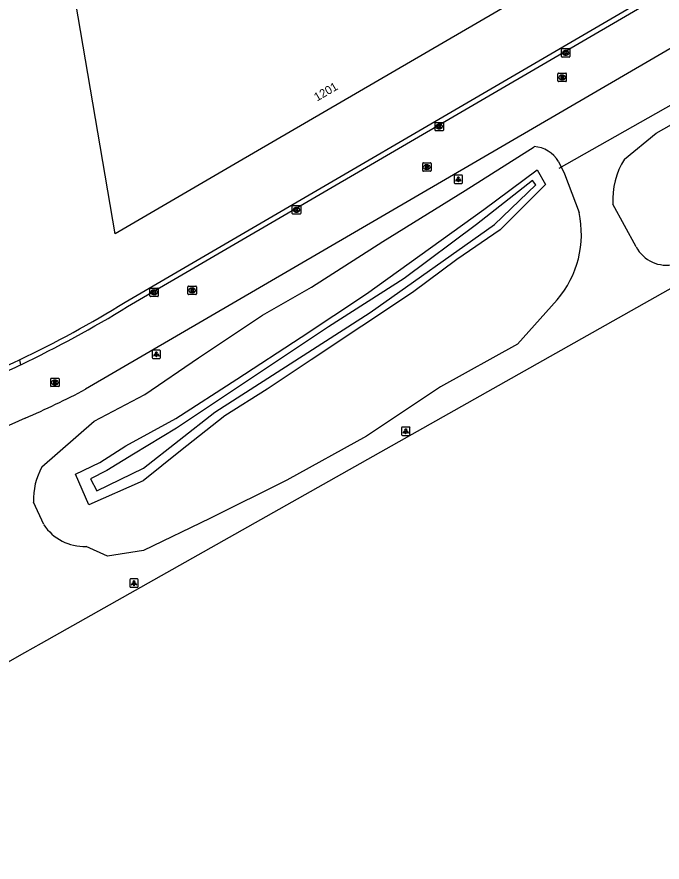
# Model space of a CAD drawing. Extents: x 154324 to 155743, y 382939 to 384183.
# Drawn here: x 154702 to 154778.5, y 382988.6 to 383088.8 of the extents above; entities that cross this region are included whole.
import ezdxf

# ---------------------------------------------------------------- set-up
doc = ezdxf.new("R2010")
doc.units = 0
for name, color, linetype in [('IMGEO_Berm_groen', 7, 'Continuous'), ('IMGEO_Duiker', 7, 'Continuous'), ('IMGEO_Fietspad_gesloten', 7, 'Continuous'), ('IMGEO_Groenvoorziening', 7, 'Continuous'), ('IMGEO_Kolk', 7, 'Continuous'), ('IMGEO_Lichtpunt', 7, 'Continuous'), ('IMGEO_Pand', 7, 'Continuous'), ('IMGEO_Pand_nummerreeks', 7, 'Continuous'), ('IMGEO_Rijbaan_lokaal_gesloten', 7, 'Continuous'), ('IMGEO_Rioolput', 7, 'Continuous'), ('IMGEO_Waterloop', 7, 'Continuous')]:
    doc.layers.add(name, color=color, linetype=linetype)

msp = doc.modelspace()

# ---------------------------------------------------------------- linework, layer by layer
at = {"layer": 'IMGEO_Berm_groen'}
for points in [[(154774.07, 383071.9), (154777.85, 383074.99), (154783.84, 383078.37), (154788.17, 383079.96), (154794.61, 383083.05), (154800.57, 383084.89)], [(154704.99, 383035.41), (154711.18, 383040.82), (154717.2, 383044.01), (154723.57, 383048.33), (154731.15, 383053.4), (154736.97, 383056.74), (154745.44, 383062.14), (154755.2, 383068.2), (154763.36, 383073.38)], [(154766.25, 383071.61), (154766.97, 383070.16), (154768.7, 383065.57)], [(154775.46, 383061.52), (154772.71, 383066.56)], [(154766.11, 383055.24), (154761.41, 383049.96), (154752.25, 383044.92), (154743.48, 383039.05), (154734.02, 383033.85), (154724.9, 383029.28), (154717.04, 383025.52), (154712.79, 383024.83), (154710.23, 383025.99)], [(154705.21, 383028.57), (154703.99, 383031.24)]]:
    msp.add_lwpolyline(points, dxfattribs=at)
for centre, radius, start, end in [((154763.18, 383069.85), 3.54, 29.8809, 87.1189), ((154781.76, 383067.09), 9.07, 147.9556, 183.3621), ((154756.95, 383063.02), 12.02, 319.6553, 12.2487), ((154779.02, 383063.34), 4, 207.0616, 284.7098), ((154711.96, 383031.54), 7.97, 150.9388, 182.1612), ((154710.06, 383031.82), 5.84, 213.8608, 271.6652)]:
    msp.add_arc(centre, radius, start, end, dxfattribs=at)
at = {"layer": 'IMGEO_Duiker'}
msp.add_lwpolyline([(154808.78, 383094.87), (154766.28, 383070.8)], dxfattribs=at)
at = {"layer": 'IMGEO_Fietspad_gesloten'}
msp.add_lwpolyline([(154658.95, 382988.56), (154668.99, 382994.18), (154672.72, 382996.39), (154679.21, 383000), (154680.53, 383000.75), (154684.21, 383002.82), (154689.55, 383005.83), (154693, 383007.77), (154702.97, 383013.4), (154704.95, 383014.51), (154806.83, 383071.94)], dxfattribs=at)
at = {"layer": 'IMGEO_Groenvoorziening'}
msp.add_lwpolyline([(154764.71, 383068.91), (154759.33, 383063.52), (154754.19, 383059.99), (154748.93, 383056.1), (154736.91, 383048.11), (154731.7, 383044.62), (154726.67, 383041.48), (154721.41, 383037.31), (154716.99, 383033.77), (154710.57, 383030.92), (154708.97, 383034.57), (154711.87, 383035.94), (154714.93, 383037.91), (154720.86, 383041.15), (154728.1, 383045.83), (154735.72, 383050.79), (154743.49, 383055.92), (154757.39, 383065.94), (154763.74, 383070.64), (154764.71, 383068.91)], dxfattribs=at)
at = {"layer": 'IMGEO_Kolk'}
for p, q in [((154766.61, 383084.08), (154766.61, 383084.94)), ((154766.68, 383085.01), (154767.54, 383085.01)), ((154767.12, 383084.23), (154767.09, 383084.23)), ((154767.1, 383084.79), (154767.12, 383084.79)), ((154767.61, 383084.94), (154767.61, 383084.08)), ((154767.54, 383084.01), (154766.68, 383084.01)), ((154751.61, 383075.35), (154751.61, 383076.2)), ((154751.68, 383076.27), (154752.54, 383076.27)), ((154752.61, 383076.2), (154752.61, 383075.35)), ((154752.54, 383075.27), (154751.68, 383075.27)), ((154752.12, 383075.49), (154752.09, 383075.49)), ((154752.1, 383076.05), (154752.12, 383076.05)), ((154734.68, 383065.47), (154734.68, 383066.32)), ((154734.75, 383066.4), (154735.61, 383066.4)), ((154735.17, 383066.18), (154735.19, 383066.18)), ((154735.68, 383066.32), (154735.68, 383065.47)), ((154735.61, 383065.4), (154734.75, 383065.4)), ((154735.19, 383065.62), (154735.16, 383065.62)), ((154717.79, 383055.69), (154717.79, 383056.55)), ((154717.87, 383056.62), (154718.72, 383056.62)), ((154718.28, 383056.4), (154718.31, 383056.4)), ((154718.8, 383056.55), (154718.8, 383055.69)), ((154718.72, 383055.62), (154717.87, 383055.62)), ((154718.3, 383055.84), (154718.28, 383055.84))]:
    msp.add_line(p, q, dxfattribs=at)
for points in [[(154766.61, 383084.08), (154766.61, 383084.94)], [(154766.68, 383085.01), (154767.54, 383085.01)], [(154766.93, 383084.71), (154767.05, 383084.71), (154767.05, 383084.56), (154767.18, 383084.71), (154767.35, 383084.71), (154767.2, 383084.56), (154767.35, 383084.31), (154767.2, 383084.31), (154767.12, 383084.47), (154767.05, 383084.41), (154767.05, 383084.31), (154766.93, 383084.31), (154766.93, 383084.71)], [(154767.61, 383084.94), (154767.61, 383084.08)], [(154767.54, 383084.01), (154766.68, 383084.01)], [(154751.61, 383075.35), (154751.61, 383076.2)], [(154751.68, 383076.27), (154752.54, 383076.27)], [(154752.61, 383076.2), (154752.61, 383075.35)], [(154752.54, 383075.27), (154751.68, 383075.27)], [(154751.93, 383075.97), (154752.05, 383075.97), (154752.05, 383075.82), (154752.18, 383075.97), (154752.35, 383075.97), (154752.2, 383075.82), (154752.35, 383075.57), (154752.2, 383075.57), (154752.12, 383075.74), (154752.05, 383075.67), (154752.05, 383075.57), (154751.93, 383075.57), (154751.93, 383075.97)], [(154734.68, 383065.47), (154734.68, 383066.32)], [(154734.75, 383066.4), (154735.61, 383066.4)], [(154735, 383066.1), (154735.12, 383066.1), (154735.12, 383065.95), (154735.25, 383066.1), (154735.42, 383066.1), (154735.27, 383065.95), (154735.42, 383065.7), (154735.27, 383065.7), (154735.19, 383065.86), (154735.12, 383065.8), (154735.12, 383065.7), (154735, 383065.7), (154735, 383066.1)], [(154735.68, 383066.32), (154735.68, 383065.47)], [(154735.61, 383065.4), (154734.75, 383065.4)], [(154717.79, 383055.69), (154717.79, 383056.55)], [(154717.87, 383056.62), (154718.72, 383056.62)], [(154718.11, 383056.32), (154718.24, 383056.32), (154718.24, 383056.17), (154718.37, 383056.32), (154718.53, 383056.32), (154718.39, 383056.17), (154718.54, 383055.92), (154718.39, 383055.92), (154718.3, 383056.08), (154718.24, 383056.02), (154718.24, 383055.92), (154718.11, 383055.92), (154718.11, 383056.32)], [(154718.8, 383056.55), (154718.8, 383055.69)], [(154718.72, 383055.62), (154717.87, 383055.62)]]:
    msp.add_lwpolyline(points, dxfattribs=at)
for centre, start, end in [((154766.68, 383084.93), 91.552, 178.448), ((154766.68, 383084.93), 91.552, 178.448), ((154766.68, 383084.09), 181.552, 268.448), ((154766.68, 383084.09), 181.552, 268.448), ((154767.53, 383084.93), 1.552, 88.448), ((154767.53, 383084.93), 1.552, 88.448), ((154767.53, 383084.09), 271.552, 358.448), ((154767.53, 383084.09), 271.552, 358.448), ((154751.69, 383076.2), 91.552, 178.448), ((154751.69, 383076.2), 91.552, 178.448), ((154752.53, 383076.2), 1.552, 88.448), ((154752.53, 383076.2), 1.552, 88.448), ((154751.69, 383075.35), 181.552, 268.448), ((154751.69, 383075.35), 181.552, 268.448), ((154752.53, 383075.35), 271.552, 358.448), ((154752.53, 383075.35), 271.552, 358.448), ((154734.75, 383066.32), 91.552, 178.448), ((154734.75, 383066.32), 91.552, 178.448), ((154735.6, 383066.32), 1.552, 88.448), ((154735.6, 383066.32), 1.552, 88.448), ((154734.75, 383065.47), 181.552, 268.448), ((154734.75, 383065.47), 181.552, 268.448), ((154735.6, 383065.47), 271.552, 358.448), ((154735.6, 383065.47), 271.552, 358.448), ((154717.87, 383056.54), 91.552, 178.448), ((154717.87, 383056.54), 91.552, 178.448), ((154718.72, 383056.54), 1.552, 88.448), ((154718.72, 383056.54), 1.552, 88.448), ((154717.87, 383055.69), 181.552, 268.448), ((154717.87, 383055.69), 181.552, 268.448), ((154718.72, 383055.69), 271.552, 358.448), ((154718.72, 383055.69), 271.552, 358.448)]:
    msp.add_arc(centre, 0.0765, start, end, dxfattribs=at)
for centre, major_axis, ratio, start_param, end_param in [((154767.1, 383084.51), (-0.387, 0.002), 0.722429, 4.712389, 7.853982), ((154767.12, 383084.51), (-0.39, 0.002), 0.717154, 1.570796, 4.712389), ((154752.1, 383075.77), (-0.387, 0.002), 0.722429, 4.712389, 7.853982), ((154752.12, 383075.77), (-0.39, 0.002), 0.717154, 1.570796, 4.712389), ((154735.17, 383065.9), (-0.387, 0.002), 0.722429, 4.712389, 7.853982), ((154735.19, 383065.9), (-0.39, 0.002), 0.717154, 1.570796, 4.712389), ((154718.28, 383056.12), (-0.387, 0.002), 0.722429, 4.712389, 7.853982), ((154718.31, 383056.12), (-0.39, 0.002), 0.717154, 1.570796, 4.712389)]:
    msp.add_ellipse(centre, major_axis=major_axis, ratio=ratio, start_param=start_param, end_param=end_param, dxfattribs=at)
at = {"layer": 'IMGEO_Lichtpunt'}
for p, q in [((154753.88, 383069.92), (154753.88, 383069.11)), ((154753.88, 383069.92), (154753.88, 383069.11)), ((154754.78, 383070.01), (154753.97, 383070.01)), ((154754.78, 383070.01), (154753.97, 383070.01)), ((154754.88, 383069.11), (154754.88, 383069.92)), ((154754.88, 383069.11), (154754.88, 383069.92)), ((154753.97, 383069.02), (154754.78, 383069.02)), ((154753.97, 383069.02), (154754.78, 383069.02)), ((154718.07, 383049.17), (154718.07, 383048.37)), ((154718.07, 383049.17), (154718.07, 383048.37)), ((154718.97, 383049.27), (154718.16, 383049.27)), ((154718.97, 383049.27), (154718.16, 383049.27)), ((154719.06, 383048.37), (154719.06, 383049.17)), ((154719.06, 383048.37), (154719.06, 383049.17)), ((154718.16, 383048.27), (154718.97, 383048.27)), ((154718.16, 383048.27), (154718.97, 383048.27)), ((154747.64, 383040.05), (154747.64, 383039.24)), ((154747.64, 383040.05), (154747.64, 383039.24)), ((154748.55, 383040.14), (154747.74, 383040.14)), ((154748.55, 383040.14), (154747.74, 383040.14)), ((154748.64, 383039.24), (154748.64, 383040.05)), ((154748.64, 383039.24), (154748.64, 383040.05)), ((154747.74, 383039.15), (154748.55, 383039.15)), ((154747.74, 383039.15), (154748.55, 383039.15)), ((154715.42, 383022.04), (154715.42, 383021.23)), ((154715.42, 383022.04), (154715.42, 383021.23)), ((154716.32, 383022.13), (154715.51, 383022.13)), ((154716.32, 383022.13), (154715.51, 383022.13)), ((154716.41, 383021.23), (154716.41, 383022.04)), ((154716.41, 383021.23), (154716.41, 383022.04)), ((154715.51, 383021.14), (154716.32, 383021.14)), ((154715.51, 383021.14), (154716.32, 383021.14))]:
    msp.add_line(p, q, dxfattribs=at)
for points in [[(154754.25, 383069.58), (154754.29, 383069.55), (154754.1, 383069.29), (154754.07, 383069.32), (154754.25, 383069.58)], [(154754.35, 383069.53), (154754.4, 383069.53), (154754.4, 383069.21), (154754.35, 383069.21), (154754.35, 383069.53)], [(154754.46, 383069.55), (154754.5, 383069.58), (154754.69, 383069.32), (154754.65, 383069.29), (154754.46, 383069.55)], [(154718.44, 383048.84), (154718.48, 383048.81), (154718.29, 383048.55), (154718.25, 383048.57), (154718.44, 383048.84)], [(154718.54, 383048.79), (154718.59, 383048.79), (154718.59, 383048.47), (154718.54, 383048.47), (154718.54, 383048.79)], [(154718.65, 383048.81), (154718.69, 383048.84), (154718.88, 383048.57), (154718.84, 383048.55), (154718.65, 383048.81)], [(154748.02, 383039.71), (154748.06, 383039.68), (154747.87, 383039.42), (154747.83, 383039.45), (154748.02, 383039.71)], [(154748.12, 383039.66), (154748.17, 383039.66), (154748.17, 383039.34), (154748.12, 383039.34), (154748.12, 383039.66)], [(154748.23, 383039.68), (154748.27, 383039.71), (154748.46, 383039.45), (154748.42, 383039.42), (154748.23, 383039.68)], [(154715.79, 383021.7), (154715.83, 383021.67), (154715.64, 383021.41), (154715.6, 383021.44), (154715.79, 383021.7)], [(154715.89, 383021.65), (154715.94, 383021.65), (154715.94, 383021.33), (154715.89, 383021.33), (154715.89, 383021.65)], [(154716, 383021.67), (154716.04, 383021.7), (154716.23, 383021.44), (154716.19, 383021.41), (154716, 383021.67)]]:
    msp.add_lwpolyline(points, dxfattribs=at)
for centre in [(154754.38, 383069.72), (154718.57, 383048.97), (154748.14, 383039.85), (154715.92, 383021.84)]:
    msp.add_circle(centre, 0.0994, dxfattribs=at)
for centre, start, end in [((154753.97, 383069.92), 90, 180), ((154753.97, 383069.92), 90, 180), ((154753.97, 383069.11), 180, 270), ((154753.97, 383069.11), 180, 270), ((154754.78, 383069.92), 0, 90), ((154754.78, 383069.92), 0, 90), ((154754.78, 383069.11), 270, 0), ((154754.78, 383069.11), 270, 360), ((154718.16, 383049.17), 90, 180), ((154718.16, 383049.17), 90, 180), ((154718.97, 383049.17), 0, 90), ((154718.97, 383049.17), 0, 90), ((154718.16, 383048.37), 180, 270), ((154718.16, 383048.37), 180, 270), ((154718.97, 383048.37), 270, 0), ((154718.97, 383048.37), 270, 360), ((154747.74, 383040.05), 90, 180), ((154747.74, 383040.05), 90, 180), ((154748.55, 383040.05), 0, 90), ((154748.55, 383040.05), 0, 90), ((154747.74, 383039.24), 180, 270), ((154747.74, 383039.24), 180, 270), ((154748.55, 383039.24), 270, 0), ((154748.55, 383039.24), 270, 360), ((154715.51, 383022.04), 90, 180), ((154715.51, 383022.04), 90, 180), ((154716.32, 383022.04), 0, 90), ((154716.32, 383022.04), 0, 90), ((154715.51, 383021.23), 180, 270), ((154715.51, 383021.23), 180, 270), ((154716.32, 383021.23), 270, 0), ((154716.32, 383021.23), 270, 360)]:
    msp.add_arc(centre, 0.0946, start, end, dxfattribs=at)
at = {"layer": 'IMGEO_Pand'}
msp.add_lwpolyline([(154761.55, 383202.29), (154766.47, 383173.5), (154749.73, 383170.63), (154750.57, 383165.74), (154750.63, 383165.35), (154755.3, 383137.94), (154772.04, 383140.8), (154777.71, 383107.67), (154758.43, 383104.38), (154760.79, 383090.49), (154728.38, 383071.61), (154713.67, 383063.04), (154708.1, 383095.79), (154696.76, 383093.86), (154680.67, 383188.5)], dxfattribs=at)
at = {"layer": 'IMGEO_Rijbaan_lokaal_gesloten'}
for points in [[(154991.53, 383204.59), (154991.29, 383204.46), (154988.64, 383202.93), (154972.99, 383194.07), (154922.65, 383165.82), (154870.56, 383136.48), (154807.99, 383101.45), (154807.41, 383100.98), (154799.35, 383096.59), (154796.65, 383095.01), (154788.62, 383090.34), (154781.16, 383085.99), (154710.18, 383044.63)], [(154714.85, 383054.94), (154776.27, 383090.74)], [(154715.15, 383054.43), (154776.57, 383090.26)], [(154641.36, 383020.72), (154644.06, 383021.92), (154701.68, 383047.8), (154702.34, 383048.11)], [(154702.34, 383048.11), (154702.47, 383047.53)], [(154641.57, 383020.14), (154644.31, 383021.37), (154701.89, 383047.26), (154702.47, 383047.53)], [(154703.01, 383041.2), (154652.03, 383018.31), (154642.78, 383014.08)]]:
    msp.add_lwpolyline(points, dxfattribs=at)
for centre, radius, start, end in [((154645.72, 383166.64), 131.36, 295.5332, 301.7538), ((154643.8, 383170.52), 136.27, 295.5044, 301.5752), ((154660.3, 383139.67), 107.34, 293.4434, 297.6884)]:
    msp.add_arc(centre, radius, start, end, dxfattribs=at)
at = {"layer": 'IMGEO_Rioolput'}
for p, q in [((154766.26, 383082.1), (154767.11, 383082.1)), ((154766.18, 383081.18), (154766.18, 383082.03)), ((154767.11, 383081.1), (154766.26, 383081.1)), ((154766.67, 383081.88), (154766.69, 383081.88)), ((154766.69, 383081.32), (154766.67, 383081.32)), ((154767.18, 383082.03), (154767.18, 383081.18)), ((154750.15, 383070.55), (154750.15, 383071.4)), ((154750.23, 383071.47), (154751.08, 383071.47)), ((154750.64, 383071.25), (154750.67, 383071.25)), ((154751.15, 383071.4), (154751.15, 383070.55)), ((154751.08, 383070.47), (154750.23, 383070.47)), ((154750.66, 383070.69), (154750.64, 383070.69)), ((154722.31, 383055.93), (154722.31, 383056.78)), ((154722.39, 383056.85), (154723.24, 383056.85)), ((154722.8, 383056.63), (154722.83, 383056.63)), ((154722.82, 383056.07), (154722.8, 383056.07)), ((154723.31, 383056.78), (154723.31, 383055.93)), ((154723.24, 383055.85), (154722.39, 383055.85)), ((154706.04, 383045), (154706.04, 383045.85)), ((154706.11, 383045.93), (154706.96, 383045.93)), ((154706.52, 383045.71), (154706.55, 383045.71)), ((154706.55, 383045.15), (154706.52, 383045.15)), ((154707.04, 383045.85), (154707.04, 383045)), ((154706.96, 383044.93), (154706.11, 383044.93))]:
    msp.add_line(p, q, dxfattribs=at)
for points in [[(154766.26, 383082.1), (154767.11, 383082.1)], [(154766.18, 383081.18), (154766.18, 383082.03)], [(154767.11, 383081.1), (154766.26, 383081.1)], [(154766.77, 383081.8), (154766.52, 383081.8), (154766.52, 383081.4)], [(154766.52, 383081.4), (154766.64, 383081.4), (154766.64, 383081.57), (154766.65, 383081.57)], [(154766.7, 383081.72), (154766.64, 383081.72), (154766.64, 383081.64)], [(154766.64, 383081.64), (154766.69, 383081.64)], [(154766.7, 383081.54), (154766.77, 383081.4), (154766.91, 383081.4), (154766.85, 383081.53)], [(154767.18, 383082.03), (154767.18, 383081.18)], [(154750.15, 383070.55), (154750.15, 383071.4)], [(154750.23, 383071.47), (154751.08, 383071.47)], [(154750.74, 383071.17), (154750.49, 383071.17), (154750.49, 383070.77)], [(154750.67, 383071.09), (154750.61, 383071.09), (154750.61, 383071.01)], [(154751.15, 383071.4), (154751.15, 383070.55)], [(154751.08, 383070.47), (154750.23, 383070.47)], [(154750.49, 383070.77), (154750.61, 383070.77), (154750.61, 383070.93), (154750.62, 383070.93)], [(154750.61, 383071.01), (154750.66, 383071.01)], [(154750.67, 383070.9), (154750.74, 383070.77), (154750.88, 383070.77), (154750.82, 383070.9)], [(154722.31, 383055.93), (154722.31, 383056.78)], [(154722.39, 383056.85), (154723.24, 383056.85)], [(154722.9, 383056.55), (154722.65, 383056.55), (154722.65, 383056.15)], [(154722.65, 383056.15), (154722.77, 383056.15), (154722.77, 383056.32), (154722.78, 383056.32)], [(154722.83, 383056.47), (154722.77, 383056.47), (154722.77, 383056.39)], [(154722.77, 383056.39), (154722.82, 383056.39)], [(154722.83, 383056.29), (154722.9, 383056.15), (154723.04, 383056.15), (154722.98, 383056.28)], [(154723.31, 383056.78), (154723.31, 383055.93)], [(154723.24, 383055.85), (154722.39, 383055.85)], [(154706.04, 383045), (154706.04, 383045.85)], [(154706.11, 383045.93), (154706.96, 383045.93)], [(154706.62, 383045.62), (154706.37, 383045.63), (154706.37, 383045.23)], [(154706.37, 383045.23), (154706.5, 383045.23), (154706.5, 383045.39), (154706.51, 383045.39)], [(154706.55, 383045.55), (154706.5, 383045.55), (154706.5, 383045.46)], [(154706.5, 383045.46), (154706.55, 383045.46)], [(154706.55, 383045.36), (154706.63, 383045.23), (154706.76, 383045.23), (154706.7, 383045.35)], [(154707.04, 383045.85), (154707.04, 383045)], [(154706.96, 383044.93), (154706.11, 383044.93)]]:
    msp.add_lwpolyline(points, dxfattribs=at)
for centre, radius, start, end in [((154766.26, 383082.03), 0.0765, 91.552, 178.448), ((154766.26, 383082.03), 0.0765, 91.552, 178.448), ((154767.11, 383082.03), 0.0765, 1.552, 88.448), ((154767.11, 383082.03), 0.0765, 1.552, 88.448), ((154766.26, 383081.18), 0.0765, 181.552, 268.448), ((154766.26, 383081.18), 0.0765, 181.552, 268.448), ((154766.65, 383081.51), 0.0533, 26.0293, 88.6989), ((154766.68, 383081.83), 0.19, 274.7715, 282.9687), ((154766.7, 383081.63), 0.0964, 77.0061, 93.1865), ((154766.72, 383081.68), 0.0378, 276.6634, 79.6772), ((154766.77, 383081.69), 0.109, 350.3612, 89.416), ((154766.77, 383081.69), 0.112, 277.5842, 350.9817), ((154766.75, 383081.48), 0.108, 29.5134, 73.7905), ((154767.11, 383081.18), 0.0765, 271.552, 358.448), ((154767.11, 383081.18), 0.0765, 271.552, 358.448), ((154750.23, 383071.4), 0.0765, 91.552, 178.448), ((154750.23, 383071.4), 0.0765, 91.552, 178.448), ((154750.67, 383070.99), 0.0964, 77.0061, 93.1865), ((154750.69, 383071.05), 0.0378, 276.6634, 79.6772), ((154750.74, 383071.06), 0.109, 350.3612, 89.416), ((154751.08, 383071.4), 0.0765, 1.552, 88.448), ((154751.08, 383071.4), 0.0765, 1.552, 88.448), ((154750.23, 383070.55), 0.0765, 181.552, 268.448), ((154750.23, 383070.55), 0.0765, 181.552, 268.448), ((154750.62, 383070.88), 0.0533, 26.0293, 88.6989), ((154750.65, 383071.2), 0.19, 274.7715, 282.9687), ((154750.74, 383071.06), 0.112, 277.5842, 350.9817), ((154750.72, 383070.84), 0.108, 29.5134, 73.7905), ((154751.08, 383070.55), 0.0765, 271.552, 358.448), ((154751.08, 383070.55), 0.0765, 271.552, 358.448), ((154722.39, 383056.78), 0.0765, 91.552, 178.448), ((154722.39, 383056.78), 0.0765, 91.552, 178.448), ((154722.78, 383056.26), 0.0533, 26.0293, 88.6989), ((154722.81, 383056.58), 0.19, 274.7715, 282.9687), ((154722.83, 383056.38), 0.0964, 77.0061, 93.1865), ((154722.85, 383056.43), 0.0378, 276.6634, 79.6772), ((154722.9, 383056.44), 0.109, 350.3612, 89.416), ((154722.9, 383056.44), 0.112, 277.5842, 350.9817), ((154722.88, 383056.23), 0.108, 29.5134, 73.7905), ((154723.24, 383056.78), 0.0765, 1.552, 88.448), ((154723.24, 383056.78), 0.0765, 1.552, 88.448), ((154722.39, 383055.93), 0.0765, 181.552, 268.448), ((154722.39, 383055.93), 0.0765, 181.552, 268.448), ((154723.24, 383055.93), 0.0765, 271.552, 358.448), ((154723.24, 383055.93), 0.0765, 271.552, 358.448), ((154706.11, 383045.85), 0.0765, 91.552, 178.448), ((154706.11, 383045.85), 0.0765, 91.552, 178.448), ((154706.11, 383045), 0.0765, 181.552, 268.448), ((154706.11, 383045), 0.0765, 181.552, 268.448), ((154706.51, 383045.34), 0.0533, 26.0293, 88.6989), ((154706.56, 383045.45), 0.0964, 77.0061, 93.1865), ((154706.53, 383045.65), 0.19, 274.7715, 282.9687), ((154706.57, 383045.51), 0.0378, 276.6634, 79.6772), ((154706.62, 383045.52), 0.109, 350.3612, 89.416), ((154706.62, 383045.51), 0.112, 277.5842, 350.9817), ((154706.61, 383045.3), 0.108, 29.5134, 73.7905), ((154706.96, 383045.85), 0.0765, 1.552, 88.448), ((154706.96, 383045.85), 0.0765, 1.552, 88.448), ((154706.96, 383045), 0.0765, 271.552, 358.448), ((154706.96, 383045), 0.0765, 271.552, 358.448)]:
    msp.add_arc(centre, radius, start, end, dxfattribs=at)
for centre, major_axis, ratio, start_param, end_param in [((154766.67, 383081.6), (-0.387, 0.002), 0.722429, 4.712389, 7.853982), ((154766.69, 383081.6), (-0.39, 0.002), 0.717154, 1.570796, 4.712389), ((154750.64, 383070.97), (-0.387, 0.002), 0.722429, 4.712389, 7.853982), ((154750.66, 383070.97), (-0.39, 0.002), 0.717154, 1.570796, 4.712389), ((154722.8, 383056.35), (-0.387, 0.002), 0.722429, 4.712389, 7.853982), ((154722.82, 383056.35), (-0.39, 0.002), 0.717154, 1.570796, 4.712389), ((154706.52, 383045.43), (-0.387, 0.002), 0.722429, 4.712389, 7.853982), ((154706.55, 383045.43), (-0.39, 0.002), 0.717154, 1.570796, 4.712389)]:
    msp.add_ellipse(centre, major_axis=major_axis, ratio=ratio, start_param=start_param, end_param=end_param, dxfattribs=at)
at = {"layer": 'IMGEO_Waterloop'}
msp.add_lwpolyline([(154763.19, 383069.38), (154756.52, 383064.16), (154747.94, 383057.75), (154738.96, 383052.02), (154720.94, 383040.02), (154715.86, 383036.92), (154712.7, 383034.99), (154710.77, 383034.01), (154711.49, 383032.57), (154717.05, 383035.28), (154725.52, 383041.89), (154743.93, 383053.73), (154758.67, 383064.16), (154763.57, 383068.85), (154763.19, 383069.38)], dxfattribs=at)

# ---------------------------------------------------------------- texts
at = {"layer": 'IMGEO_Pand_nummerreeks'}
msp.add_text('1201', height=1, rotation=30.2121, dxfattribs=at).set_placement((154737.62, 383078.73))

doc.saveas('drawing.dxf')
